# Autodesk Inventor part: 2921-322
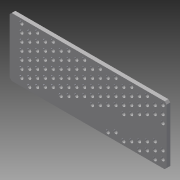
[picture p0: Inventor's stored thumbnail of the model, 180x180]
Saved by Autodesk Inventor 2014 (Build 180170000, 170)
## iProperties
Company: NHTSA/VRTC
Created: 2012-02
Part Number: 2921-322
Material: Steel
Document SubType Name: Modeling
Designer: Mike Vanvoorhis
Density: 7.85 g/cm^3
Project: CHILD SIDE IMPACT SLED
Description: BENCH STOP PLATE
Mass: 3855.78 g
Surface Area: 1450.83 cm^2
Volume: 491.182 cm^3
Stock Number: PL 9.5 (3/8") x 150.0 (5 7/8") x 400.0 (15 3/4")
Appearance: Steel
DESIGN DATE: 2012-11-05
Author: Dave Walker
Title: Bench Stop Plate
Subject: Child Side Impact Sled
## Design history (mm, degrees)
sketch "Sketch1"
  geometry: L1 (-200, 0)-(200, 0); L2 (200, 0)-(200, -9.5); L3 (200, -9.5)-(-200, -9.5); L4 (-200, -9.5)-(-200, 0); L5 (0, 1.9)-(0, -11.4) reference; L6 (-280, 0)-(280, 0) reference
  constraints: 8 end point, 2 parallel, 1 collinear, 1 horizontal, 1 perpendicular, 1 other
  dimensions: "d0" = 400 distance of L1.start L1.end; "d1" = 9.5 distance of L3.end L1.start
extrude "Extrusion1" new body sketch "Sketch1" distance "d2" = 150; taper "d3" = 0 deg
chamfer "Chamfer1" distance "d4" = 5; stored, may be unused: second distance "d5" = 2, angle "d6" = 45 deg
sketch "Sketch3"
  geometry: L1 (0, 0)-(390, 0) reference; L2 (-5, 5)-(-5, 145) reference; 2 further points
  dimensions: "d18" = 20 distance from line of point (25, 20) L1; "d19" = 30 distance from line of point (25, 20) L2
hole "Hole2" sketch "Sketch3" at (25, 20) diameter "d21" = 10; stored, may be unused: countersink angle "d25" = 90 deg, drill point angle "d27" = 118 deg; dims "d22" = 6, "d23" = 4, "d24" = 2, "d26" = 8
sketch "Sketch4"
  geometry: L1 (0, 0)-(390, 0) reference; L2 (-5, 5)-(-5, 145) reference; 2 further points
  dimensions: "d34" = 10 distance from line of point (45, 10) L1; "d35" = 50 distance from line of point (45, 10) L2
hole "Hole3" sketch "Sketch4" at (45, 10) diameter "d36" = 10; stored, may be unused: countersink angle "d40" = 90 deg, drill point angle "d42" = 118 deg; dims "d37" = 6, "d38" = 4, "d39" = 2, "d41" = 8
sketch "Sketch2"
  geometry: L1 (0, 0)-(390, 0) reference; L2 (-5, 5)-(-5, 145) reference; 3 further points
  constraints: 1 horizontal alignment
  dimensions: "d7" = 70 distance from line of point (65, 70) L1; "d8" = 70 distance from line of point (65, 70) L2; "d9" = 80 distance of point (145, 70) point (65, 70)
hole "Hole1" sketch "Sketch2" at (65, 70), (145, 70) diameter "d10" = 30; stored, may be unused: countersink angle "d14" = 90 deg, drill point angle "d16" = 118 deg; dims "d11" = 6, "d12" = 4, "d13" = 2, "d15" = 8
body "Solid1"
pattern_linear "Rectangular Pattern1" dims "d30" = 40
pattern_linear "Rectangular Pattern2" dims "d45" = 40
